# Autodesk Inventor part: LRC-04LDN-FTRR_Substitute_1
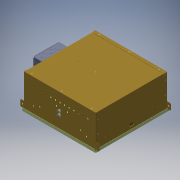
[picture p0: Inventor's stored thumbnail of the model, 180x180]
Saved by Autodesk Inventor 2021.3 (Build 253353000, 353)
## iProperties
Part Number: LRC-04LDN-FTRR_Substitute_1
Material: Generic
Document SubType Name: Modeling
Designer: JChurch
Manufacturer: Standard
Standards Organization: Custom
Density: 1 g/cm^3
Appearance: Smooth - Black
Author: JChurch
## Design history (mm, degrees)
derived "LRC-04LDN-FTRR.iam"
body "Solid9"
node "830520-00-00.ipt:1"
node "881088-00-00.iam:1::830140-00-00.ipt:1"
body "Solid10"
node "881088-00-00.iam:1::850014-00-00.iam:1::805044-00-00.ipt:1"
body "Solid11"
node "881088-00-00.iam:1::850014-00-00.iam:1::805174-00-00.ipt:1"
body "Solid12"
node "881088-00-00.iam:1::850014-00-00.iam:1::502055-00-00.ipt:1"
body "Solid13"
node "881088-00-00.iam:1::850014-00-00.iam:1::502055-00-00.ipt:2"
body "Solid14"
node "881088-00-00.iam:1::850014-00-00.iam:1::507032-00-00.ipt:1"
body "Solid15"
node "881088-00-00.iam:1::507000-00-00.ipt:1"
body "Solid16"
node "881088-00-00.iam:1::507000-00-00.ipt:2"
body "Solid17"
node "881088-00-00.iam:1::506002-00-00.ipt:1"
body "Solid18"
node "881088-00-00.iam:1::506002-00-00.ipt:2"
body "Solid19"
node "881088-00-00.iam:1::506002-00-00.ipt:3"
body "Solid20"
node "881088-00-00.iam:1::506002-00-00.ipt:4"
body "Solid21"
node "881088-00-00.iam:1::506002-00-00.ipt:5"
body "Solid22"
node "881088-00-00.iam:1::506002-00-00.ipt:6"
body "Solid23"
node "881088-00-00.iam:1::506002-00-00.ipt:7"
body "Solid24"
node "881088-00-00.iam:1::506002-00-00.ipt:8"
body "Solid25"
node "881088-00-00.iam:1::506002-00-00.ipt:9"
body "Solid26"
node "881088-00-00.iam:1::506002-00-00.ipt:10"
body "Solid27"
node "881088-00-00.iam:1::506002-00-00.ipt:11"
body "Solid28"
node "881088-00-00.iam:1::506002-00-00.ipt:12"
body "Solid29"
node "881088-00-00.iam:1::506002-00-00.ipt:13"
body "Solid30"
node "881088-00-00.iam:1::506002-00-00.ipt:14"
body "Solid31"
node "881088-00-00.iam:1::830392-01-00.iam:1::830392-00-00.ipt:1"
body "Solid32"
node "881088-00-00.iam:1::830392-01-00.iam:1::500027-00-00.ipt:1"
body "Solid33"
node "881088-00-00.iam:1::830392-01-00.iam:1::501030-00-00.ipt:1"
body "Solid34"
node "881088-00-00.iam:1::830392-01-00.iam:1::500027-00-00.ipt:2"
body "Solid35"
node "881088-00-00.iam:1::830392-01-00.iam:1::501030-00-00.ipt:2"
body "Solid36"
node "881088-00-00.iam:1::830392-01-00.iam:1::501030-00-00.ipt:3"
body "Solid37"
node "881088-00-00.iam:1::830392-01-00.iam:1::501030-00-00.ipt:4"
body "Solid38"
node "881088-00-00.iam:1::830392-01-00.iam:2::830392-00-00.ipt:1"
body "Solid39"
node "881088-00-00.iam:1::830392-01-00.iam:2::500027-00-00.ipt:1"
body "Solid40"
node "881088-00-00.iam:1::830392-01-00.iam:2::501030-00-00.ipt:1"
body "Solid41"
node "881088-00-00.iam:1::830392-01-00.iam:2::500027-00-00.ipt:2"
body "Solid42"
node "881088-00-00.iam:1::830392-01-00.iam:2::501030-00-00.ipt:2"
body "Solid43"
node "881088-00-00.iam:1::830392-01-00.iam:2::501030-00-00.ipt:3"
body "Solid44"
node "881088-00-00.iam:1::830392-01-00.iam:2::501030-00-00.ipt:4"
body "Solid45"
node "750480-FT-XX.iam:1::740103-50-00.ipt:1"
body "Solid46"
node "750480-FT-XX.iam:1::507035-01-38.ipt:1"
body "Solid47"
node "750480-FT-XX.iam:1::510051-00-00.ipt:1"
body "Solid48"
node "750480-FT-XX.iam:1::700483-01-20.ipt:1"
body "Solid49"
node "750480-FT-XX.iam:1::725379-00-00.ipt:1"
body "Solid50"
node "750480-FT-XX.iam:1::507035-01-38.ipt:2"
body "Solid51"
node "750480-FT-XX.iam:1::510052-00-00_65.ipt:1"
body "Solid52"
other parameters: "d15" = 61.595, "d16" = 9.525, "d17" = 9.525, "d35" = 5.08
